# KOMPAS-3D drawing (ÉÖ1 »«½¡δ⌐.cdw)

Referenced files: РЩ1.cdw
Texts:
  Электроснабжение первой детской клинической больницы  по адресу: г. Иваново, ул. Мальцева д.3
  Microsoft
  Текст на чертеже
  Размерные надписи
  Шероховатость
  Линия-выноска #1
  Линия-выноска #2
  Линия-выноска #3
  Отклонения формы и база
  Заголовок таблицы
  Ячейка таблицы
  Стрелка вида
  Обозначение изменения
  Фигурная скобка
  Номер узла
  Марка координационной оси
  VRCB
  Выносная надпись
  Обозначение узла
  Марка/позиционное обозначение с линией-выноской
  Марка/позиционное обозначение на линии
  Марка/позиционное обозначение без линии-выноски
  ВА 47-29 (1)
  ВА 47-29 (3)
  Номер группы
  Р кВт
  Ток, А
  Гр16
  Гр17
  Гр18
  Гр19
  Освещение
  ВВГнгLS 5х10 мм 2  скрыто в ПВХ
  трубе от ВРУ
  ВВГнгLS 3х1,5 cкрыто
  РЩ-1(ЩРН-48)
  Гр20
  Гр21
  Гр22
  Гр23
  Гр24
  АД12М
  Гр25
  Гр26
  Гр27
  Гр28
  Гр29
  Гр30
  Розетки
  ВВГнгLS 3х2,5 cкрыто
  CONTINUOUS0
  Электроснабжение первой детской клинической больницы
  по адресу: г. Иваново, ул. Мальцева д.3
  ГИП
  Разработ
  Однолинейная расчётная схема щита
  РЩ-1
  Кочетков
  ООО "Мастер Лайт"
Dimensions and other numbers on the sheet: 2012-0011-ЭС; 7; 10А; 20А; 0.5; 0.43; 1.1; 5.05; 0.4; 0.28; 0.21; 16А Iсраб=30мА; 0.7; 0.3; 0.6; 4; 1:1; 5; 0; 1; 2; 3; 6; 8; 9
